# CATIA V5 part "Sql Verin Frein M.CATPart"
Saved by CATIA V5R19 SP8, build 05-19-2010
Part number: Sql Verin Frein M
Publications: "Droite.1", "Point.4"
Bounding box of the stored display mesh (mm): x 0 to 0, y -1370 to 0, z -1500 to -1500
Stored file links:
  G:\EU_thinkMotion\CFAO_2010\MMS_groupe3\MMS_groupe3\rdalborgo\rdalborgo\Sql Verin Frein M.CATPart
  G:\EU_thinkMotion\CFAO_2010\MMS_groupe3\MMS_groupe3\rdalborgo\rdalborgo\rdalborgo.CATProduct
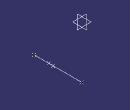
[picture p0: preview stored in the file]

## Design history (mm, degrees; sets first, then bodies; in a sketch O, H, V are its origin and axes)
Set1
  Point1 "A verin frein": linked copy from another document
  Point2 "B verin frein": linked copy from another document
  Point3: linked copy from another document
Set2
  Line1: type PtPt, FirstPoint Point3, SecondPoint Point2
  Point4: type OnCurve, Support Line1, Ratio 0.4
Body1 (main body)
